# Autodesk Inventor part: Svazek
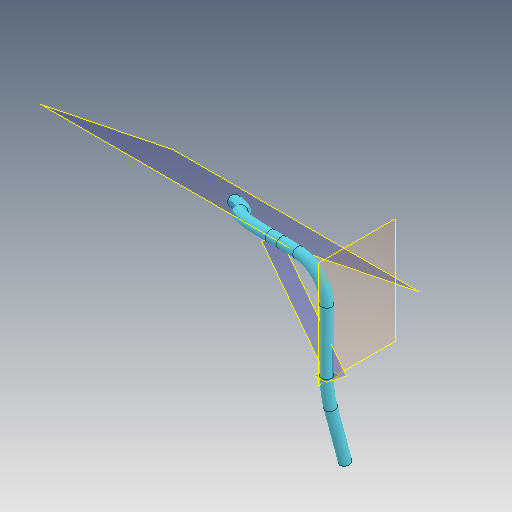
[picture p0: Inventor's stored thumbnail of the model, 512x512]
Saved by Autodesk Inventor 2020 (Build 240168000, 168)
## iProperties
Created: 2025-04
Part Number: Svazek
Material: Polyetylen, S vysokou hustotou
Document SubType Name: Modeling
Designer: doma
Density: 0.952 g/cm^3
Appearance: Kadetská modrá
Mass: 150.225 g
Surface Area: 355.756 cm^2
Volume: 157.8 cm^3
Author: doma
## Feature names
1. Tažení1
2. Tažení2
## Parameters: d1 = 8 mm, d4 = 18 mm, d5 = 0, d6 = 0, d9 = 15 deg, d11 = 0, d12 = 0
